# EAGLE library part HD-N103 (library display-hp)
LED DISPLAY 1-character 7 segment, decimal point right
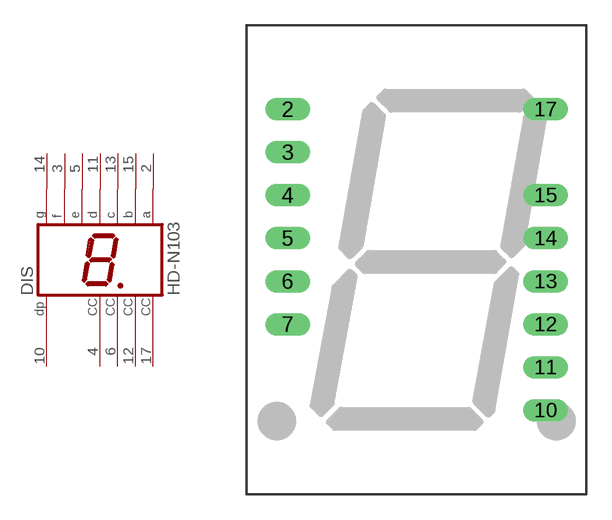
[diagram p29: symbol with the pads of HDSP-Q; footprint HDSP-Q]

Designator prefix DIS

## HD-N103 (OC_FARNELL: unknown; OC_NEWARK: unknown)  [HDSP-Q]
2  A  pas
3  F  pas
4  CC  pas
5  E  pas
6  CC  pas
10  DP  pas
11  D  pas
12  CC  pas
13  C  pas
14  G  pas
15  B  pas
17  CC  pas

## Footprint HDSP-Q (pad centres in mm)
LED DISPLAY 20-mm 1 character 7 segment, 2 decimal points
drill 0.813 long: 2 -7.62,8.89; 3 -7.62,6.35; 4 -7.62,3.81; 5 -7.62,1.27; 6 -7.62,-1.27; 7 -7.62,-3.81; 10 7.62,-8.89; 11 7.62,-6.35; 12 7.62,-3.81; 13 7.62,-1.27; 14 7.62,1.27; 15 7.62,3.81; 17 7.62,8.89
